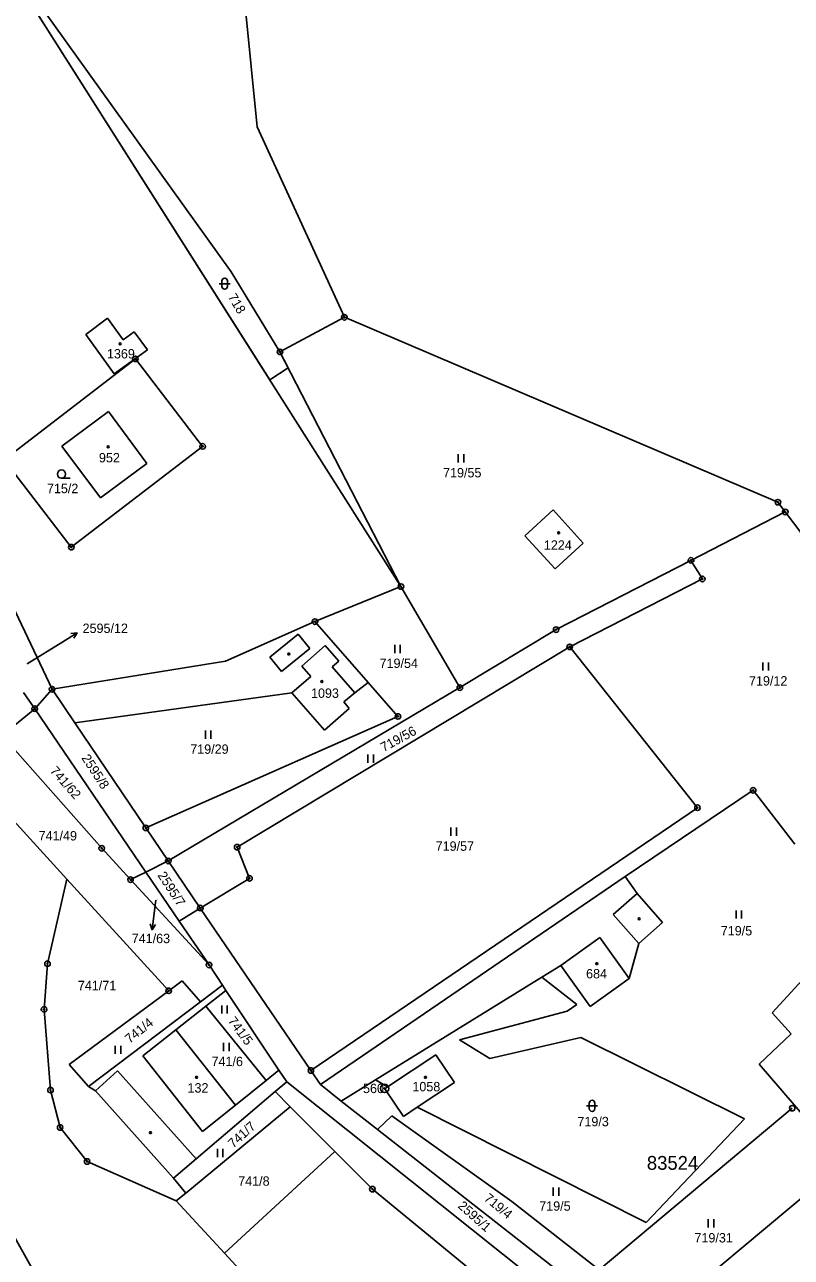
# Model space of a CAD drawing. Extents: x -439246 to -433691, y -1130252 to -1121148.
# Drawn here: x -436784.3 to -436645.4, y -1125806.8 to -1125583.4 of the extents above; entities that cross this region are included whole.
import ezdxf

# ---------------------------------------------------------------- set-up
doc = ezdxf.new("R2010")
doc.units = 0
for name, color, linetype in [('Vrstva 1', 7, 'Continuous'), ('Vrstva 16', 7, 'Continuous'), ('Vrstva 17', 7, 'Continuous'), ('Vrstva 18', 7, 'Continuous'), ('Vrstva 19', 7, 'Continuous'), ('Vrstva 24', 7, 'Continuous'), ('Vrstva 25', 7, 'Continuous'), ('Vrstva 3', 7, 'Continuous'), ('Vrstva 37', 7, 'Continuous'), ('Vrstva 4', 7, 'Continuous'), ('Vrstva 52', 7, 'Continuous'), ('Vrstva 53', 7, 'Continuous'), ('Vrstva 6', 7, 'Continuous')]:
    doc.layers.add(name, color=color, linetype=linetype)

msp = doc.modelspace()

# ---------------------------------------------------------------- linework, layer by layer
at = {"layer": 'Vrstva 1'}
for p, q in [((-436773.2, -1125639.56), (-436769.26, -1125636.61)), ((-436769.26, -1125636.61), (-436766.43, -1125640.55)), ((-436766.43, -1125640.55), (-436764.41, -1125639.1)), ((-436764.41, -1125639.1), (-436762.02, -1125642.37)), ((-436768.05, -1125646.73), (-436773.2, -1125639.56)), ((-436762.02, -1125642.37), (-436768.05, -1125646.73)), ((-436788.32, -1125712.23), (-436782.46, -1125707.4)), ((-436788.32, -1125712.23), (-436770.31, -1125732.7)), ((-436770.31, -1125732.7), (-436765.09, -1125738.38)), ((-436765.09, -1125738.38), (-436762.33, -1125737)), ((-436780.14, -1125753.62), (-436776.65, -1125738.29)), ((-436765.09, -1125738.38), (-436750.88, -1125753.84)), ((-436780.76, -1125761.89), (-436780.14, -1125753.62)), ((-436779.6, -1125776.52), (-436780.76, -1125761.89)), ((-436777.85, -1125783.3), (-436779.6, -1125776.52)), ((-436772.96, -1125789.46), (-436777.85, -1125783.3)), ((-436756.8, -1125796.62), (-436772.96, -1125789.46)), ((-436722.99, -1125833.29), (-436748.07, -1125806.1))]:
    msp.add_line(p, q, dxfattribs=at)
for points in [[(-436794.11, -1125562.36), (-436746.84, -1125628.19)], [(-436716.11, -1125685.26), (-436794.11, -1125562.36)], [(-436746.84, -1125628.19), (-436738.02, -1125642.72)], [(-436738.02, -1125642.72), (-436726.36, -1125636.45)], [(-436726.36, -1125636.45), (-436647.82, -1125669.97)], [(-436738.02, -1125642.72), (-436716.11, -1125685.26)], [(-436788.01, -1125662.26), (-436764.22, -1125643.99)], [(-436752.03, -1125659.85), (-436764.22, -1125643.99)], [(-436777.53, -1125659.8), (-436769.1, -1125653.55)], [(-436769.1, -1125653.55), (-436762.13, -1125662.94)], [(-436777.53, -1125659.8), (-436770.56, -1125669.2)], [(-436775.82, -1125678.12), (-436752.03, -1125659.85)], [(-436775.82, -1125678.12), (-436788.01, -1125662.26)], [(-436770.56, -1125669.2), (-436762.13, -1125662.94)], [(-436796.47, -1125667.67), (-436779.31, -1125703.88)], [(-436647.82, -1125669.97), (-436646.49, -1125671.73)], [(-436688.51, -1125671.38), (-436693.65, -1125676.05)], [(-436683.07, -1125677.4), (-436688.51, -1125671.38)], [(-436663.57, -1125680.51), (-436646.49, -1125671.73)], [(-436646.49, -1125671.73), (-436629.17, -1125694.64)], [(-436693.65, -1125676.05), (-436688.17, -1125682.07)], [(-436688.17, -1125682.07), (-436683.07, -1125677.4)], [(-436688, -1125693.06), (-436663.57, -1125680.51)], [(-436663.57, -1125680.51), (-436661.51, -1125683.88)], [(-436716.11, -1125685.26), (-436731.68, -1125691.61)], [(-436705.44, -1125703.58), (-436716.11, -1125685.26)], [(-436661.51, -1125683.88), (-436685.54, -1125696.19)], [(-436747.9, -1125698.77), (-436731.68, -1125691.61)], [(-436722.04, -1125702.64), (-436731.68, -1125691.61)], [(-436705.44, -1125703.58), (-436688, -1125693.06)], [(-436685.54, -1125696.19), (-436745.78, -1125732.49)], [(-436662.4, -1125725.35), (-436685.54, -1125696.19)], [(-436779.31, -1125703.88), (-436747.9, -1125698.77)], [(-436779.31, -1125703.88), (-436782.46, -1125707.4)], [(-436775.19, -1125709.97), (-436779.31, -1125703.88)], [(-436758.25, -1125735), (-436705.44, -1125703.58)], [(-436724.44, -1125704.55), (-436722.04, -1125702.64)], [(-436716.65, -1125708.8), (-436722.04, -1125702.64)], [(-436784.48, -1125704.43), (-436782.46, -1125707.4)], [(-436775.19, -1125709.97), (-436735.88, -1125704.53)], [(-436735.88, -1125704.53), (-436729.97, -1125711.28)], [(-436726.48, -1125706.16), (-436724.44, -1125704.55)], [(-436782.46, -1125707.4), (-436762.33, -1125737)], [(-436729.97, -1125711.28), (-436725.46, -1125707.33)], [(-436725.46, -1125707.33), (-436726.48, -1125706.16)], [(-436776.65, -1125738.29), (-436803.28, -1125709.03)], [(-436762.32, -1125729), (-436775.19, -1125709.97)], [(-436762.32, -1125729), (-436716.65, -1125708.8)], [(-436675.5, -1125737.8), (-436652.3, -1125722.19)], [(-436652.3, -1125722.19), (-436644.75, -1125731.93)], [(-436732.42, -1125772.98), (-436662.4, -1125725.35)], [(-436758.25, -1125735), (-436762.32, -1125729)], [(-436745.78, -1125732.49), (-436743.54, -1125738.15)], [(-436758.25, -1125735), (-436762.33, -1125737)], [(-436752.46, -1125743.53), (-436758.25, -1125735)], [(-436762.33, -1125737), (-436756.28, -1125745.9)], [(-436758.18, -1125758.52), (-436776.65, -1125738.29)], [(-436743.54, -1125738.15), (-436752.46, -1125743.53)], [(-436675.5, -1125737.8), (-436730.7, -1125775.51)], [(-436673.33, -1125740.89), (-436675.5, -1125737.8)], [(-436673.33, -1125740.89), (-436668.71, -1125746.15)], [(-436752.46, -1125743.53), (-436756.28, -1125745.9)], [(-436752.46, -1125743.53), (-436732.42, -1125772.98)], [(-436756.28, -1125745.9), (-436750.88, -1125753.84)], [(-436668.71, -1125746.15), (-436673.03, -1125749.94)], [(-436633.18, -1125745.44), (-436648.84, -1125762.52)], [(-436673.03, -1125749.94), (-436674.77, -1125756.28)], [(-436750.88, -1125753.84), (-436748.43, -1125757.53)], [(-436687.16, -1125753.96), (-436690.6, -1125756.08)], [(-436687.16, -1125753.96), (-436681.83, -1125761.36)], [(-436758.18, -1125758.52), (-436755.73, -1125756.7)], [(-436755.73, -1125756.7), (-436752.41, -1125760.53)], [(-436690.6, -1125756.08), (-436720.69, -1125774.67)], [(-436684.27, -1125761.02), (-436690.6, -1125756.08)], [(-436681.83, -1125761.36), (-436674.77, -1125756.28)], [(-436776.2, -1125771.88), (-436758.18, -1125758.52)], [(-436748.43, -1125757.53), (-436752.41, -1125760.53)], [(-436751.47, -1125761.33), (-436747.82, -1125758.45)], [(-436748.43, -1125757.53), (-436747.82, -1125758.45)], [(-436747.82, -1125758.45), (-436738.2, -1125772.94)], [(-436752.41, -1125760.53), (-436772.72, -1125775.86)], [(-436756.86, -1125765.58), (-436751.47, -1125761.33)], [(-436740.5, -1125774.8), (-436751.47, -1125761.33)], [(-436685.97, -1125762.2), (-436684.27, -1125761.02)], [(-436705.49, -1125767.4), (-436685.97, -1125762.2)], [(-436648.84, -1125762.52), (-436645.45, -1125766.35)], [(-436746.05, -1125779.28), (-436756.86, -1125765.58)], [(-436645.45, -1125766.35), (-436651.23, -1125771.85)], [(-436700.03, -1125770.77), (-436705.49, -1125767.4)], [(-436683.51, -1125766.97), (-436700.03, -1125770.77)], [(-436653.85, -1125781.72), (-436683.51, -1125766.97)], [(-436709.79, -1125770.11), (-436718.54, -1125775.94)], [(-436706.43, -1125775.14), (-436709.79, -1125770.11)], [(-436772.72, -1125775.86), (-436776.2, -1125771.88)], [(-436740.5, -1125774.8), (-436738.2, -1125772.94)], [(-436738.2, -1125772.94), (-436736.81, -1125775.04)], [(-436730.7, -1125775.51), (-436732.42, -1125772.98)], [(-436651.23, -1125771.85), (-436626.2, -1125800.88)], [(-436746.05, -1125779.28), (-436740.5, -1125774.8)], [(-436738.87, -1125776.8), (-436736.81, -1125775.04)], [(-436736.81, -1125775.04), (-436680.95, -1125819.62)], [(-436720.69, -1125774.67), (-436726.92, -1125778.52)], [(-436718.54, -1125775.94), (-436720.69, -1125774.67)], [(-436713.15, -1125779.62), (-436706.43, -1125775.14)], [(-436771.46, -1125776.63), (-436772.72, -1125775.86)], [(-436757.3, -1125792.49), (-436771.46, -1125776.63)], [(-436753.21, -1125789.01), (-436738.87, -1125776.8)], [(-436736.15, -1125779.54), (-436738.87, -1125776.8)], [(-436730.7, -1125775.51), (-436726.92, -1125778.52)], [(-436718.54, -1125775.94), (-436719.03, -1125776.27)], [(-436719.03, -1125776.27), (-436715.67, -1125781.3)], [(-436755.07, -1125795.19), (-436736.15, -1125779.54)], [(-436736.15, -1125779.54), (-436728.06, -1125787.67)], [(-436726.92, -1125778.52), (-436720.38, -1125783.64)], [(-436715.67, -1125781.3), (-436713.15, -1125779.62)], [(-436713.15, -1125779.62), (-436671.67, -1125800.5)], [(-436680.2, -1125809.12), (-436645.23, -1125779.81)], [(-436720.38, -1125783.64), (-436717.76, -1125781.17)], [(-436717.76, -1125781.17), (-436696.05, -1125796.71)], [(-436671.67, -1125800.5), (-436653.85, -1125781.72)], [(-436720.38, -1125783.64), (-436683.9, -1125812.22)], [(-436728.06, -1125787.67), (-436748.07, -1125806.1)], [(-436721.28, -1125794.48), (-436728.06, -1125787.67)], [(-436757.3, -1125792.49), (-436753.21, -1125789.01)], [(-436755.07, -1125795.19), (-436757.3, -1125792.49)], [(-436674.68, -1125822.17), (-436637.55, -1125791.1)], [(-436756.8, -1125796.62), (-436755.07, -1125795.19)], [(-436688.05, -1125821.82), (-436721.28, -1125794.48)], [(-436748.07, -1125806.1), (-436756.8, -1125796.62)], [(-436696.05, -1125796.71), (-436680.2, -1125809.12)]]:
    msp.add_lwpolyline(points, dxfattribs=at)
at = {"layer": 'Vrstva 16'}
for p, q in [((-436777.33, -1125695.25), (-436774.78, -1125693.67)), ((-436760.82, -1125744.47), (-436761.18, -1125747.45))]:
    msp.add_line(p, q, dxfattribs=at)
for points in [[(-436775.89, -1125693.77), (-436774.78, -1125693.67), (-436775.37, -1125694.62)], [(-436783.82, -1125699.26), (-436777.33, -1125695.25)], [(-436760.53, -1125742.08), (-436760.82, -1125744.47)], [(-436760.56, -1125746.52), (-436761.18, -1125747.45), (-436761.55, -1125746.4)]]:
    msp.add_lwpolyline(points, dxfattribs=at)
at = {"layer": 'Vrstva 24'}
for centre, radius in [((-436726.36, -1125636.45), 0.5), ((-436726.36, -1125636.45), 0.1), ((-436764.22, -1125643.99), 0.5), ((-436738.02, -1125642.72), 0.5), ((-436738.02, -1125642.72), 0.1), ((-436764.22, -1125643.99), 0.1), ((-436752.03, -1125659.85), 0.5), ((-436752.03, -1125659.85), 0.1), ((-436647.82, -1125669.97), 0.5), ((-436647.82, -1125669.97), 0.1), ((-436646.49, -1125671.73), 0.5), ((-436646.49, -1125671.73), 0.1), ((-436775.82, -1125678.12), 0.5), ((-436775.82, -1125678.12), 0.1), ((-436663.57, -1125680.51), 0.5), ((-436663.57, -1125680.51), 0.1), ((-436661.51, -1125683.88), 0.5), ((-436661.51, -1125683.88), 0.1), ((-436716.11, -1125685.26), 0.5), ((-436716.11, -1125685.26), 0.1), ((-436731.68, -1125691.61), 0.5), ((-436731.68, -1125691.61), 0.1), ((-436688, -1125693.06), 0.5), ((-436688, -1125693.06), 0.1), ((-436685.54, -1125696.19), 0.5), ((-436685.54, -1125696.19), 0.1), ((-436779.31, -1125703.88), 0.5), ((-436779.31, -1125703.88), 0.1), ((-436705.44, -1125703.58), 0.5), ((-436705.44, -1125703.58), 0.1), ((-436782.46, -1125707.4), 0.5), ((-436782.46, -1125707.4), 0.1), ((-436716.65, -1125708.8), 0.5), ((-436716.65, -1125708.8), 0.1), ((-436652.3, -1125722.19), 0.5), ((-436652.3, -1125722.19), 0.1), ((-436662.4, -1125725.35), 0.5), ((-436662.4, -1125725.35), 0.1), ((-436762.32, -1125729), 0.5), ((-436762.32, -1125729), 0.1), ((-436770.31, -1125732.7), 0.5), ((-436770.31, -1125732.7), 0.1), ((-436745.78, -1125732.49), 0.5), ((-436745.78, -1125732.49), 0.1), ((-436758.25, -1125735), 0.5), ((-436758.25, -1125735), 0.1), ((-436765.09, -1125738.38), 0.5), ((-436765.09, -1125738.38), 0.1), ((-436743.54, -1125738.15), 0.5), ((-436743.54, -1125738.15), 0.1), ((-436752.46, -1125743.53), 0.5), ((-436752.46, -1125743.53), 0.1), ((-436780.14, -1125753.62), 0.5), ((-436780.14, -1125753.62), 0.1), ((-436750.88, -1125753.84), 0.5), ((-436750.88, -1125753.84), 0.1), ((-436758.18, -1125758.52), 0.5), ((-436758.18, -1125758.52), 0.1), ((-436780.76, -1125761.89), 0.5), ((-436780.76, -1125761.89), 0.1), ((-436732.42, -1125772.98), 0.5), ((-436732.42, -1125772.98), 0.1), ((-436779.6, -1125776.52), 0.5), ((-436779.6, -1125776.52), 0.1), ((-436719.05, -1125776.22), 0.75), ((-436719.05, -1125776.22), 0.1), ((-436645.23, -1125779.81), 0.5), ((-436777.85, -1125783.3), 0.5), ((-436777.85, -1125783.3), 0.1), ((-436772.96, -1125789.46), 0.5), ((-436772.96, -1125789.46), 0.1), ((-436721.28, -1125794.48), 0.5), ((-436721.28, -1125794.48), 0.1)]:
    msp.add_circle(centre, radius, dxfattribs=at)
at = {"layer": 'Vrstva 25'}
for p, q in [((-436748.54, -1125630.86), (-436748.54, -1125629.86)), ((-436747.54, -1125629.86), (-436747.54, -1125630.86)), ((-436749.04, -1125630.36), (-436747.04, -1125630.36)), ((-436705.74, -1125662.77), (-436705.74, -1125661.27)), ((-436704.74, -1125662.77), (-436704.74, -1125661.27)), ((-436777.6, -1125665.63), (-436776, -1125665.63)), ((-436717.24, -1125697.31), (-436717.24, -1125695.81)), ((-436716.24, -1125697.31), (-436716.24, -1125695.81)), ((-436650.55, -1125700.5), (-436650.55, -1125699)), ((-436649.55, -1125700.5), (-436649.55, -1125699)), ((-436751.53, -1125712.87), (-436751.53, -1125711.37)), ((-436750.53, -1125712.87), (-436750.53, -1125711.37)), ((-436722.08, -1125717.18), (-436722.08, -1125715.68)), ((-436721.08, -1125717.18), (-436721.08, -1125715.68)), ((-436707.07, -1125730.45), (-436707.07, -1125728.95)), ((-436706.07, -1125730.45), (-436706.07, -1125728.95)), ((-436655.4, -1125745.45), (-436655.4, -1125743.95)), ((-436654.4, -1125745.45), (-436654.4, -1125743.95)), ((-436748.56, -1125762.67), (-436748.56, -1125761.17)), ((-436747.56, -1125762.67), (-436747.56, -1125761.17)), ((-436767.86, -1125769.98), (-436767.86, -1125768.48)), ((-436766.86, -1125769.98), (-436766.86, -1125768.48)), ((-436748.23, -1125769.48), (-436748.23, -1125767.98)), ((-436747.23, -1125769.48), (-436747.23, -1125767.98)), ((-436682.49, -1125779.38), (-436680.49, -1125779.38)), ((-436681.99, -1125779.88), (-436681.99, -1125778.88)), ((-436680.99, -1125778.88), (-436680.99, -1125779.88)), ((-436749.37, -1125788.69), (-436749.37, -1125787.19)), ((-436748.37, -1125788.69), (-436748.37, -1125787.19)), ((-436688.52, -1125795.7), (-436688.52, -1125794.2)), ((-436687.52, -1125795.7), (-436687.52, -1125794.2)), ((-436660.43, -1125801.44), (-436660.43, -1125799.94)), ((-436659.43, -1125801.44), (-436659.43, -1125799.94))]:
    msp.add_line(p, q, dxfattribs=at)
for centre, radius in [((-436766.98, -1125641.24), 0.175), ((-436769.14, -1125659.93), 0.175), ((-436777.6, -1125664.88), 0.75), ((-436687.54, -1125675.51), 0.175), ((-436736.43, -1125697.48), 0.175), ((-436730.43, -1125702.48), 0.175), ((-436672.96, -1125745.48), 0.175), ((-436680.64, -1125753.61), 0.175), ((-436753.13, -1125774.21), 0.175), ((-436711.68, -1125774.21), 0.175), ((-436761.5, -1125784.24), 0.175)]:
    msp.add_circle(centre, radius, dxfattribs=at)
for centre, start, end in [((-436748.04, -1125629.86), 0, 180), ((-436748.04, -1125630.86), 180, 0), ((-436681.49, -1125778.88), 0, 180), ((-436681.49, -1125779.88), 180, 0)]:
    msp.add_arc(centre, 0.5, start, end, dxfattribs=at)
at = {"layer": 'Vrstva 3'}
for points in [[(-436773.2, -1125639.56), (-436769.26, -1125636.61)], [(-436769.26, -1125636.61), (-436766.43, -1125640.55)], [(-436766.43, -1125640.55), (-436764.41, -1125639.1)], [(-436764.41, -1125639.1), (-436762.02, -1125642.37)], [(-436768.05, -1125646.73), (-436773.2, -1125639.56)], [(-436762.02, -1125642.37), (-436768.05, -1125646.73)], [(-436777.53, -1125659.8), (-436769.1, -1125653.55)], [(-436769.1, -1125653.55), (-436762.13, -1125662.94)], [(-436777.53, -1125659.8), (-436770.56, -1125669.2)], [(-436770.56, -1125669.2), (-436762.13, -1125662.94)], [(-436688.51, -1125671.38), (-436693.65, -1125676.05)], [(-436683.07, -1125677.4), (-436688.51, -1125671.38)], [(-436693.65, -1125676.05), (-436688.17, -1125682.07)], [(-436688.17, -1125682.07), (-436683.07, -1125677.4)], [(-436729.82, -1125695.97), (-436734.07, -1125699.69)], [(-436729.82, -1125695.97), (-436727.38, -1125698.75)], [(-436728.59, -1125699.81), (-436727.38, -1125698.75)], [(-436735.88, -1125704.53), (-436732.46, -1125701.53)], [(-436732.46, -1125701.53), (-436734.07, -1125699.69)], [(-436724.44, -1125704.55), (-436728.59, -1125699.81)], [(-436735.88, -1125704.53), (-436729.97, -1125711.28)], [(-436726.48, -1125706.16), (-436724.44, -1125704.55)], [(-436729.97, -1125711.28), (-436725.46, -1125707.33)], [(-436725.46, -1125707.33), (-436726.48, -1125706.16)], [(-436687.16, -1125753.96), (-436680.1, -1125748.88)], [(-436680.1, -1125748.88), (-436674.77, -1125756.28)], [(-436687.16, -1125753.96), (-436681.83, -1125761.36)], [(-436681.83, -1125761.36), (-436674.77, -1125756.28)], [(-436756.86, -1125765.58), (-436762.87, -1125770.32)], [(-436746.05, -1125779.28), (-436756.86, -1125765.58)], [(-436762.87, -1125770.32), (-436752.06, -1125784.02)], [(-436709.79, -1125770.11), (-436718.54, -1125775.94)], [(-436706.43, -1125775.14), (-436709.79, -1125770.11)], [(-436713.15, -1125779.62), (-436706.43, -1125775.14)], [(-436718.54, -1125775.94), (-436719.03, -1125776.27)], [(-436719.03, -1125776.27), (-436715.67, -1125781.3)], [(-436746.05, -1125779.28), (-436752.06, -1125784.02)], [(-436715.67, -1125781.3), (-436713.15, -1125779.62)]]:
    msp.add_lwpolyline(points, dxfattribs=at)
at = {"layer": 'Vrstva 37'}
for centre in [(-436766.98, -1125641.24), (-436769.14, -1125659.93), (-436687.54, -1125675.51), (-436730.43, -1125702.48), (-436680.64, -1125753.61), (-436753.13, -1125774.21), (-436711.68, -1125774.21)]:
    msp.add_circle(centre, 0.175, dxfattribs=at)
at = {"layer": 'Vrstva 4'}
for points in [[(-436734.74, -1125693.87), (-436739.85, -1125698.04)], [(-436734.74, -1125693.87), (-436732.62, -1125696.46)], [(-436732.62, -1125696.46), (-436737.73, -1125700.64)], [(-436729.82, -1125695.97), (-436734.07, -1125699.69)], [(-436729.82, -1125695.97), (-436727.38, -1125698.75)], [(-436739.85, -1125698.04), (-436737.73, -1125700.64)], [(-436728.59, -1125699.81), (-436727.38, -1125698.75)], [(-436735.88, -1125704.53), (-436732.46, -1125701.53)], [(-436732.46, -1125701.53), (-436734.07, -1125699.69)], [(-436724.44, -1125704.55), (-436728.59, -1125699.81)], [(-436673.33, -1125740.89), (-436677.65, -1125744.68)], [(-436677.65, -1125744.68), (-436673.03, -1125749.94)], [(-436687.16, -1125753.96), (-436680.1, -1125748.88)], [(-436680.1, -1125748.88), (-436674.77, -1125756.28)], [(-436756.86, -1125765.58), (-436762.87, -1125770.32)], [(-436762.87, -1125770.32), (-436752.06, -1125784.02)], [(-436771.46, -1125776.63), (-436767.45, -1125773.05)], [(-436767.45, -1125773.05), (-436753.21, -1125789.01)], [(-436746.05, -1125779.28), (-436752.06, -1125784.02)]]:
    msp.add_lwpolyline(points, dxfattribs=at)
at = {"layer": 'Vrstva 52'}
for points in [[(-436629.17, -1125694.64), (-436646.49, -1125671.73), (-436647.82, -1125669.97), (-436726.36, -1125636.45), (-436738.02, -1125642.72), (-436736.53, -1125645.6), (-436739.89, -1125647.79), (-436794.11, -1125562.36)], [(-436876.45, -1125628.41), (-436864.82, -1125639.9), (-436858.55, -1125646.09), (-436848.96, -1125653.33), (-436839.59, -1125662.28), (-436828.09, -1125676.76), (-436822.55, -1125684.65), (-436817.65, -1125693.17), (-436816.74, -1125695.23), (-436813.04, -1125703.58), (-436804.44, -1125722.99), (-436802.1, -1125732.37), (-436798.26, -1125756.22), (-436795.92, -1125764.75), (-436795.78, -1125765.85), (-436794.86, -1125773.27), (-436792.99, -1125781.45), (-436790.38, -1125792.86), (-436788.04, -1125799.68), (-436779.94, -1125814.17)]]:
    msp.add_lwpolyline(points, dxfattribs=at)
at = {"layer": 'Vrstva 6'}
for points in [[(-436742.16, -1125601.95), (-436748.81, -1125535.04)], [(-436726.36, -1125636.45), (-436742.16, -1125601.95)]]:
    msp.add_lwpolyline(points, dxfattribs=at)

# ---------------------------------------------------------------- texts
at = {"layer": 'Vrstva 16'}
for s, p in [('2595/12', (-436773.78, -1125693.67)), ('741/49', (-436781.75, -1125731.28)), ('741/63', (-436764.88, -1125749.89)), ('719/5', (-436691.06, -1125798.39))]:
    msp.add_text(s, height=1.7, dxfattribs=at).set_placement(p)
msp.add_text('2595/1', height=1.7, rotation=318.2894, dxfattribs=at).set_placement((-436705.92, -1125797.71))
at = {"layer": 'Vrstva 17'}
msp.add_text('560', height=1.7, dxfattribs=at).set_placement((-436722.98, -1125777.07))
at = {"layer": 'Vrstva 18'}
for s, rotation, p in [('718', 300.7314, (-436747.52, -1125632.75)), ('719/56', 28.7443, (-436719.23, -1125715.29)), ('2595/8', 303.0393, (-436774.05, -1125716.33)), ('741/62', 311.4, (-436779.79, -1125718.74)), ('2595/7', 303.0393, (-436760.27, -1125737.59)), ('741/4', 38.7572, (-436765.25, -1125768.16)), ('741/5', 306.8486, (-436747.55, -1125764.01)), ('741/7', 42.0079, (-436746.49, -1125787.13)), ('719/4', 320.5015, (-436701.2, -1125796.39))]:
    msp.add_text(s, height=1.7, rotation=rotation, dxfattribs=at).set_placement(p)
for s, height, p in [('719/55', 1.7, (-436708.48, -1125665.47)), ('715/2', 1.7, (-436780.24, -1125668.33)), ('2595/12', 0.1, (-436784.07, -1125699.26)), ('719/54', 1.7, (-436719.98, -1125700.01)), ('719/12', 1.7, (-436653.06, -1125703.2)), ('719/29', 1.7, (-436754.28, -1125715.57)), ('719/57', 1.7, (-436709.82, -1125733.15)), ('741/63', 0.1, (-436760.53, -1125742.08)), ('719/5', 1.7, (-436658.17, -1125748.49)), ('741/71', 1.7, (-436774.64, -1125758.42)), ('741/6', 1.7, (-436750.42, -1125772.18)), ('719/3', 1.7, (-436684.14, -1125783.08)), ('741/8', 1.7, (-436745.59, -1125793.86)), ('719/31', 1.7, (-436662.94, -1125804.14))]:
    msp.add_text(s, height=height, dxfattribs=at).set_placement(p)
at = {"layer": 'Vrstva 19'}
for s, p in [('1369', (-436769.37, -1125643.91)), ('952', (-436770.82, -1125662.75)), ('1224', (-436690.22, -1125678.59)), ('1093', (-436732.4, -1125705.43)), ('684', (-436682.57, -1125756.28)), ('132', (-436754.77, -1125776.97)), ('1058', (-436714.04, -1125776.75))]:
    msp.add_text(s, height=1.7, dxfattribs=at).set_placement(p)
at = {"layer": 'Vrstva 53'}
msp.add_text('83524', height=2.5, dxfattribs=at).set_placement((-436671.56, -1125790.97))

doc.saveas('drawing.dxf')
